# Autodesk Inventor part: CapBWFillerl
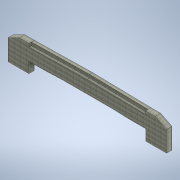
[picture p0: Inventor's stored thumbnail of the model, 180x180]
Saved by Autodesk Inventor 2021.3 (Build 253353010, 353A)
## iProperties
Created: 2021-11
Part Number: CapBWFillerl
Material: Concrete, Cast-in-Place, Gray
Document SubType Name: Modeling
Designer: u1426
Density: 2.40731 g/cm^3
Appearance: Flat - Gray 1
Author: u1426
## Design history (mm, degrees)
sketch "Sketch1"
  geometry: L1 (-5505.45, 0)-(-5505.45, 1016); L2 (5505.45, 0)-(5505.45, 1016); L3 (5505.45, 1016)-(3962.4, 1016); L4 (-5505.45, 1016)-(-3962.4, 1016); L5 (-3962.4, 1016)-(-2336.8, 1076.96); L6 (-2336.8, 1076.96)-(2336.8, 1076.96); L7 (2336.8, 1076.96)-(3962.4, 1016); L8 (-5505.45, 0)-(-7467.6, 0); L9 (-7467.6, 0)-(-7467.6, 1943.1); L10 (5505.45, 0)-(7467.6, 0); L11 (7467.6, 0)-(7467.6, 1936.75); L12 (6400.8, 2470.15)-(5486.4, 2470.15); L13 (5486.4, 2470.15)-(0, 2586.228); L14 (-6400.8, 2476.5)-(-5486.4, 2476.5); L15 (-5486.4, 2476.5)-(0, 2586.228); L16 (-6400.8, 2476.5)-(-7467.6, 1943.1); L17 (6400.8, 2470.15)-(7467.6, 1936.75); 3 further points
  constraints: 34 end point, 5 horizontal, 4 perpendicular, 4 point on line, 2 vertical, 1 collinear
  dimensions: "d0" = 5505.45 distance of point (0, 0) L1.start; "d4" = 1543.05 distance of L2.end L3.end; "d5" = 1543.05 distance of L1.end L4.end; "d6" = 1625.6 horizontal distance of L6.end L3.end; "d7" = 1625.6 horizontal distance of L4.end L5.end; "d8" = 4673.6 distance of L5.end L6.end (derived); "d9" = 2336.8 horizontal distance of L5.end point (0, 0) (derived); "d10" = 60.96 vertical distance of L4.end L5.end; "d30" = 5505.45 distance from line of point (0, 0) L2; "d31" = 1016 distance of L1.start L1.end; "d32" = 1016 distance of L2.start L2.end; "d33" = 1962.15 distance of L1.start L8.end; "d34" = 2476.5 distance of L8.end point (-7467.6, 2476.5); "d35" = 1962.15 distance of L2.start L10.end; "d36" = 2470.15 distance of L10.end point (7467.6, 2470.15); "d37" = 1981.2 distance of point (7467.6, 2470.15) L12.end; "d38" = 1981.2 distance of point (-7467.6, 2476.5) L14.end; "d39" = 5486.4 horizontal distance of L14.end L13.end; "d41" = 5486.4 horizontal distance of L12.end L13.end; "d42" = 109.728 vertical distance of L14.end L13.end; "d43" = 1066.8 distance of L14.start point (-7467.6, 2476.5); "d44" = 533.4 distance of L9.end point (-7467.6, 2476.5); "d45" = 1066.8 distance of L12.start point (7467.6, 2470.15) (= d43); "d46" = 533.4 distance of L11.end point (7467.6, 2470.15) (= d44)
extrude "Extrusion1" new body sketch "Sketch1" distance "d11" = 508; taper "d12" = 0 deg
sketch "Sketch3"
  geometry: L1 (0, 2586.228)-(-5486.4, 2476.5) reference; L2 (5486.4, 2470.15)-(0, 2586.228) reference; L3 (-5486.4, 2476.5)-(0, 2586.228) reference; L4 (-5486.4, 2476.5)-(-5486.4, 2171.7); L5 (5486.4, 2470.15)-(5486.4, 2165.35); L6 (5486.4, 2165.35)-(0, 2281.428); L7 (0, 2281.428)-(-5486.4, 2171.7); 1 further point
  constraints: 8 end point, 2 parallel, 2 vertical
  dimensions: "d47" = 304.8 distance of L1.end L4.end; "d48" = 304.8 distance of L2.start L5.end
extrude "Extrusion2" cut sketch "Sketch3" distance "d49" = 228.6; taper "d50" = 0 deg
body "Solid1"
